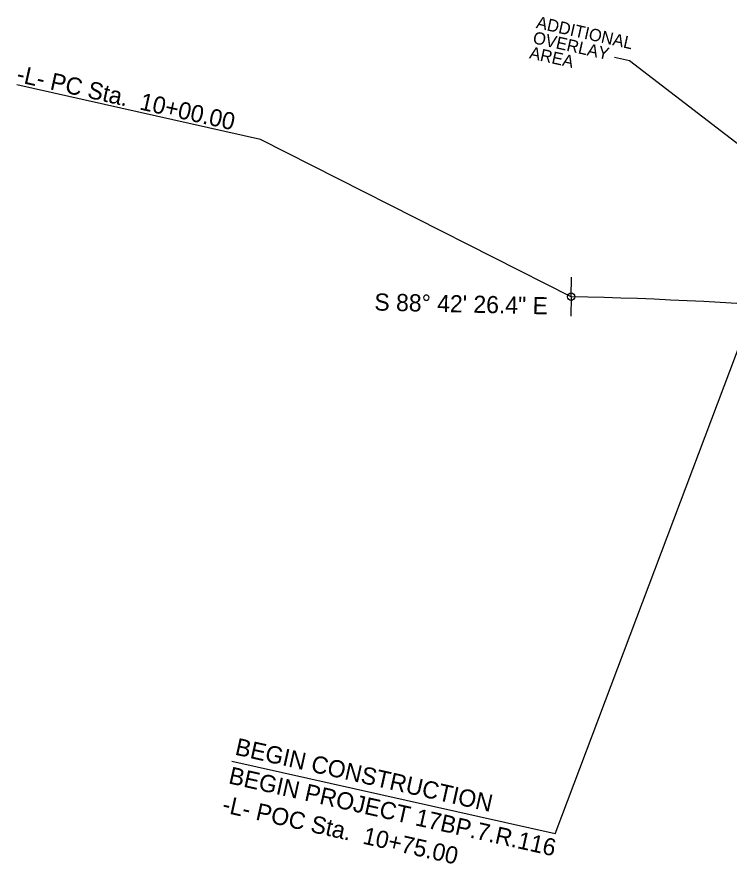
# Model space of a CAD drawing. Extents: x 1784740 to 1786163, y 841056 to 841833.
# Drawn here: x 1784740 to 1785030.5, y 841329.6 to 841675 of the extents above; entities that cross this region are included whole.
import ezdxf

# ---------------------------------------------------------------- set-up
doc = ezdxf.new("R2010")
doc.units = 0
for name, color, linetype in [('Prop Dimension', 7, 'Continuous'), ('Prop Horizontal Alignment', 7, 'Continuous'), ('Prop Horizontal Alignment Direction Label', 7, 'Continuous'), ('Prop Horizontal Alignment Station Label', 7, 'Continuous'), ('Prop Horizontal Alignment Tick Large', 7, 'Continuous')]:
    doc.layers.add(name, color=color, linetype=linetype)

msp = doc.modelspace()

# ---------------------------------------------------------------- linework, layer by layer
at = {"layer": 'Prop Dimension'}
for p, q in [((1784983.75, 841658.56), (1784989.97, 841657.17)), ((1784989.97, 841657.17), (1785090.18, 841580))]:
    msp.add_line(p, q, dxfattribs=at)
at = {"layer": 'Prop Horizontal Alignment'}
msp.add_arc((1784924.4, 839711.38), 1850, 75.31501, 88.70732, dxfattribs=at)
at = {"layer": 'Prop Horizontal Alignment Station Label'}
for p, q in [((1784839.45, 841625.05), (1784740.03, 841647.34)), ((1784966.14, 841560.91), (1784839.45, 841625.05)), ((1784959.55, 841341.9), (1785041.06, 841557.69)), ((1784959.55, 841341.9), (1784827.77, 841371.45))]:
    msp.add_line(p, q, dxfattribs=at)
msp.add_circle((1784966.14, 841560.91), 1.5, dxfattribs=at)
at = {"layer": 'Prop Horizontal Alignment Tick Large'}
for q in [(1784966.32, 841568.9), (1784965.96, 841552.91)]:
    msp.add_line((1784966.14, 841560.91), q, dxfattribs=at)

# ---------------------------------------------------------------- texts
at = {"layer": 'Prop Dimension'}
for s, p in [('ADDITIONAL', (1784951.57, 841670.49)), ('OVERLAY', (1784950.18, 841664.3)), ('AREA', (1784948.79, 841658.12))]:
    msp.add_text(s, height=5, rotation=347.3599, dxfattribs=at).set_placement(p)
at = {"layer": 'Prop Horizontal Alignment Direction Label'}
msp.add_text('S 88%%d 42\' 26.4" E', height=7, rotation=358.7073, dxfattribs=at).set_placement((1784885.8, 841555.27))
at = {"layer": 'Prop Horizontal Alignment Station Label'}
for s, p in [('-L- PC Sta.  10+00.00', (1784739.48, 841648.57)), ('BEGIN CONSTRUCTION', (1784828.65, 841374.25)), ('BEGIN PROJECT 17BP.7.R.116', (1784826.02, 841362.54)), ('-L- POC Sta.  10+75.00', (1784823.39, 841350.83))]:
    msp.add_text(s, height=7, rotation=347.3599, dxfattribs=at).set_placement(p)

doc.saveas('drawing.dxf')
